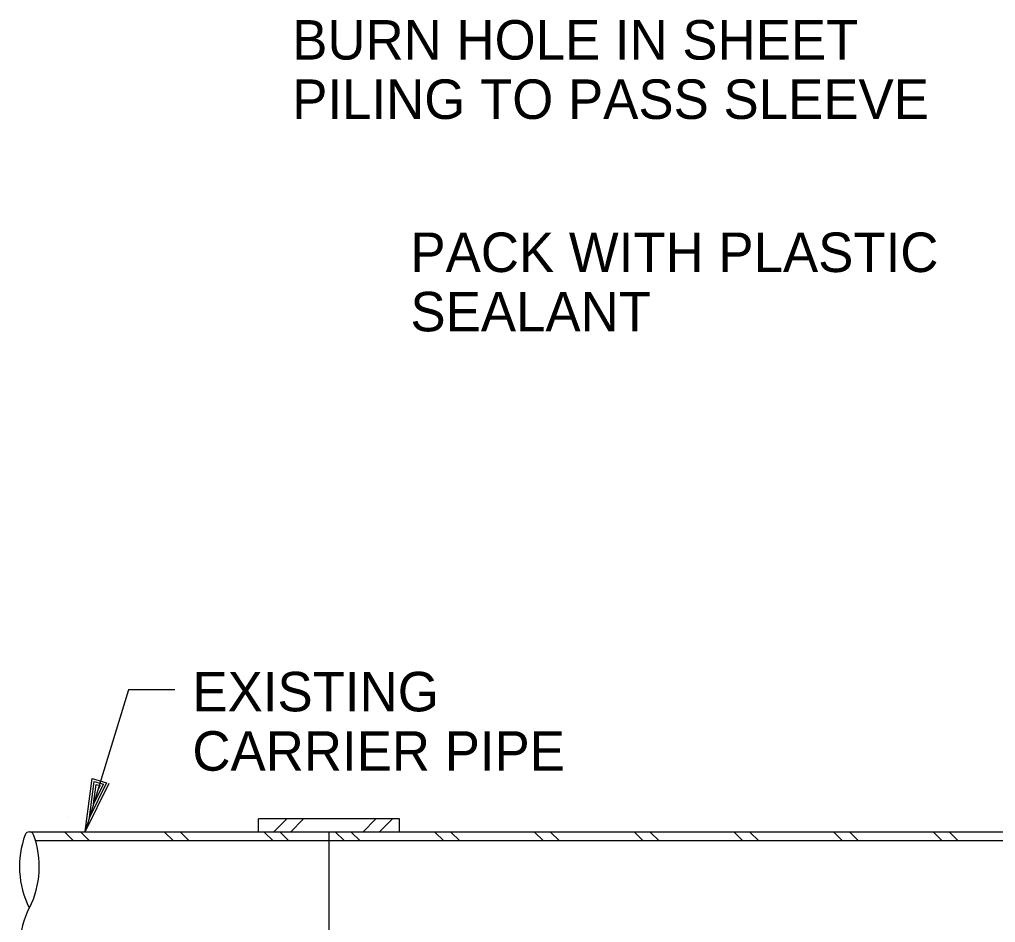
# Model space of a CAD drawing. Extents: x 22339.2 to 22413.4, y 22369.6 to 22418.8.
# Drawn here: x 22339.239 to 22343.853, y 22396.66 to 22400.928 of the extents above; entities that cross this region are included whole.
import ezdxf

# ---------------------------------------------------------------- set-up
doc = ezdxf.new("R2010")
doc.units = 0
for name, color, linetype in [('Level 1', 7, 'Continuous'), ('Level 2', 7, 'Continuous'), ('Level 4', 7, 'Continuous'), ('Level 8', 7, 'Continuous')]:
    doc.layers.add(name, color=color, linetype=linetype)

msp = doc.modelspace()

# ---------------------------------------------------------------- linework, layer by layer
at = {"layer": 'Level 1'}
msp.add_line((22339.4667, 22397.1572), (22339.4667, 22397.1572), dxfattribs=at)
for centre, radius, start, end in [((22339.6744, 22396.9239), 0.4356, 159.8064, 206.6071), ((22339.2856, 22397.0669), 0.0213, 20.1936, 159.8064), ((22338.8968, 22396.9239), 0.4356, 333.3929, 20.1936), ((22339.6744, 22396.5336), 0.4356, 153.3929, 200.1919)]:
    msp.add_arc(centre, radius, start, end, dxfattribs=at)
at = {"layer": 'Level 2'}
for p, q in [((22340.3691, 22397.0875), (22340.3691, 22397.15)), ((22341.0357, 22397.15), (22340.3691, 22397.15)), ((22341.0357, 22397.0875), (22341.0357, 22397.15)), ((22345.9524, 22397.0875), (22339.2857, 22397.0875)), ((22345.9524, 22397.0458), (22339.315, 22397.0458)), ((22340.7024, 22396.3688), (22340.7024, 22397.0875))]:
    msp.add_line(p, q, dxfattribs=at)
for points in [[(22339.9734, 22397.7589), (22339.7544, 22397.7589), (22339.5489, 22397.0902)], [(22339.6617, 22397.3164), (22339.5489, 22397.0902), (22339.5827, 22397.3406), (22339.6502, 22397.3199), (22339.5693, 22397.1564), (22339.5923, 22397.3265), (22339.6356, 22397.3132), (22339.5889, 22397.2202), (22339.6019, 22397.3124), (22339.6197, 22397.3069), (22339.6092, 22397.2864)]]:
    msp.add_lwpolyline(points, dxfattribs=at)
at = {"layer": 'Level 8'}
for p, q in [((22339.5693, 22397.1564), (22339.5693, 22397.1564)), ((22339.5489, 22397.0902), (22339.5489, 22397.0902))]:
    msp.add_line(p, q, dxfattribs=at)
for points in [[(22340.5024, 22397.15), (22340.4399, 22397.0875)], [(22340.5821, 22397.15), (22340.5196, 22397.0875)], [(22340.9243, 22397.15), (22340.8618, 22397.0875)], [(22341.0019, 22397.15), (22340.9394, 22397.0875)], [(22339.4947, 22397.0458), (22339.453, 22397.0875)], [(22339.5701, 22397.0458), (22339.5284, 22397.0875)], [(22339.9661, 22397.0458), (22339.9244, 22397.0875)], [(22340.0415, 22397.0458), (22339.9999, 22397.0875)], [(22340.4375, 22397.0458), (22340.3958, 22397.0875)], [(22340.5129, 22397.0458), (22340.4713, 22397.0875)], [(22340.7751, 22397.0458), (22340.7334, 22397.0875)], [(22340.8488, 22397.0458), (22340.8071, 22397.0875)], [(22341.2447, 22397.0458), (22341.2031, 22397.0875)], [(22341.3202, 22397.0458), (22341.2785, 22397.0875)], [(22341.7161, 22397.0458), (22341.6745, 22397.0875)], [(22341.7916, 22397.0458), (22341.7499, 22397.0875)], [(22342.1875, 22397.0458), (22342.1459, 22397.0875)], [(22342.263, 22397.0458), (22342.2213, 22397.0875)], [(22342.659, 22397.0458), (22342.6173, 22397.0875)], [(22342.7344, 22397.0458), (22342.6927, 22397.0875)], [(22343.1304, 22397.0458), (22343.0887, 22397.0875)], [(22343.2058, 22397.0458), (22343.1641, 22397.0875)], [(22343.6018, 22397.0458), (22343.5601, 22397.0875)], [(22343.6772, 22397.0458), (22343.6355, 22397.0875)]]:
    msp.add_lwpolyline(points, dxfattribs=at)

# ---------------------------------------------------------------- texts
at = {"layer": 'Level 4'}
for s, height, p in [('BURN HOLE IN SHEET', 0.186667, (22340.5282, 22400.7384)), ('PILING TO PASS SLEEVE', 0.186667, (22340.5282, 22400.4579)), ('PACK WITH PLASTIC', 0.186667, (22341.0871, 22399.7343)), ('SEALANT', 0.18667, (22341.0871, 22399.4539)), ('EXISTING', 0.18667, (22340.0562, 22397.6577)), ('CARRIER PIPE', 0.186667, (22340.0562, 22397.3772))]:
    msp.add_text(s, height=height, dxfattribs=at).set_placement(p)

doc.saveas('drawing.dxf')
